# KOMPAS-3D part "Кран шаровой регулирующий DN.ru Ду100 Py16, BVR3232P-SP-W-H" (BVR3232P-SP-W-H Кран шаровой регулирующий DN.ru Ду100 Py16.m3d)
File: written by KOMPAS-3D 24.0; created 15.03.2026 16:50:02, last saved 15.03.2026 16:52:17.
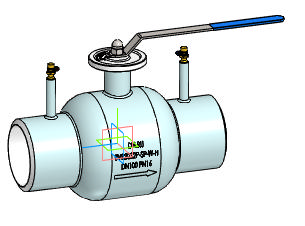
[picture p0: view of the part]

Document properties: Автор: Максим; Полное имя файла: D:\Rabota ebanaya\BVR3232P-SP-W-H Кран шаровой регулирующий Ду15-150\Типоразмеры\DN100\BVR3232P-SP-W-H Кран шаровой регулирующий DN.ru Ду100 Py16.m3d

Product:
- Body: Тело 1  | qty 1
    Масса: 23.303183
- Part/product: Кран шаровой регулирующий DN.ru Ду100 Py16  | designation BVR3232P-SP-W-H
    Масса: 12.1
    Раздел спецификации: Прочие изделия
    Примечание: D160-69414

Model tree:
1. Операция без истории:1

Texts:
  BVR3232P-SP-W-H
